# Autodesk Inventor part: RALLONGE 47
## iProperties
Created: 2004-11
Part Number: RALLONGE 47
Document SubType Name: Modeling
Designer: Bruno
Manufacturer: Standard
Standards Organization: Custom
Author: Bruno
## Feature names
1. Base1
